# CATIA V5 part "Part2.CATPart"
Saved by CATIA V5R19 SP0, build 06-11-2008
Part number: Part1.1
Bounding box of the stored display mesh (mm): x -60 to 30, y -435.613 to 219.055, z -12.333 to 56.576
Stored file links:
  D:\thinkmotion-MPB\Dropbox\CIAO82010_JCF\BELAZOUZ\548-belazouz\Part2.CATPart
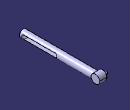
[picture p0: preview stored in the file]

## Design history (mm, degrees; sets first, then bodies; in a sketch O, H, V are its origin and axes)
Body1 (main body)
  Sketch1 on yz-plane, origin (0, 0, 0), H (0, 1, 0), V (0, 0, 1)
    line L1 (164.3871, 20.7358) -> (-435.6129, 20.7358)
    line L2 (164.3871, 20.7358) -> (164.3871, -9.2642)
    line L3 (164.3871, -9.2642) -> (-435.6129, -9.2642)
    line L4 (-435.6129, -9.2642) -> (-435.6129, 20.7358)
    length L1 = 600
    length L2 = 30
    horizontal: L1 H, L3 H
    vertical: L2 V, L4 V
  Shaft1: profile Sketch1, axis Sketch1.L1, angle 360
  Sketch2 on yz-plane, origin (0, 0, 0), H (0, 1, 0), V (0, 0, 1)
    circle A1 centre (184.5966, 22.1176) radius 34.458
  Pad1: profile Sketch2, direction (1, 0, 0), length 30, opposite side length 30
  Sketch3 on yz-plane, origin (0, 0, 0), H (0, 1, 0), V (0, 0, 1)
    construction line L1 (-404.2173, 19.9697) -> (-145.6188, 19.9697)
    line L2 (-404.2173, 35.7358) -> (-145.6188, 35.7358)
    line L3 (-145.6188, 4.2036) -> (-404.2173, 4.2036)
    arc A1 centre (-145.6188, 19.9697) radius 15.7661 from (-145.6188, 35.7358) to (-145.6188, 4.2036) cw
    arc A2 centre (-404.2173, 19.9697) radius 15.7661 from (-404.2173, 4.2036) to (-404.2173, 35.7358) cw
    reference projected line E1 through (0, 20.7358) direction (-1, 0) from axis of face of Shaft1 from Sketch1.L3
    distance L1 L2 = 15.7661
    distance L2 E1 = 15
    horizontal: L1 H
    tangency: A1 L2, A2 L2, A1 L3, A2 L3
  Pocket1: profile Sketch3, direction (1, 0, 0), length 30, opposite side length 36
  Sketch4 on start face of Pad1, origin (-30, 0, 0), H (0, -1, 0), V (0, 0, 1)
    circle A1 centre (-184.5314, 21.5881) radius 10
    point P1 (-184.5314, 21.5881)
    reference projected circle E1 centre (-184.5966, 22.1176) radius 34.458 from edge [start face of Pad1 | face of Pad1 from Sketch2.A1]
    reference projected circle E2 centre (-184.5966, 22.1176) radius 34.458 from edge [start face of Pad1 | face of Pad1 from Sketch2.A1]
    distance P1 E1 = 33.9245
    radius E2 = 34.458 (reference)
    radius A1 = 10
  Pad2: profile Sketch4, direction (-1, 0, 0), length 30
  Point1: stored without definition
  Line1: type PtDir, RefPoint Point1, Direction edge [face of Shaft1 from Sketch1.L3 | face of Pocket1 from Sketch3.L3], Start 0, End 250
